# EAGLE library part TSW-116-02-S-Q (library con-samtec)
THROUGH-HOLE .025" SQ POST HEADER Source: Samtec TSW.pdf
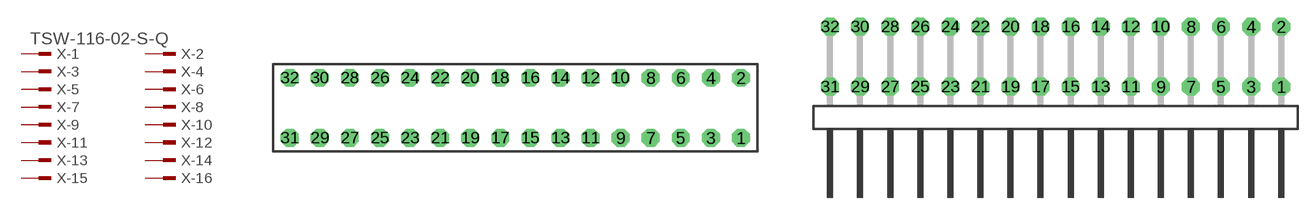
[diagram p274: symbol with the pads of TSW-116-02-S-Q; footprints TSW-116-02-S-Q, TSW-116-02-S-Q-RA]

Designator prefix X; gates -1=MPINV -2=MPIN -3=MPIN -4=MPIN -5=MPIN -6=MPIN -7=MPIN -8=MPIN -9=MPIN -10=MPIN -11=MPIN -12=MPIN -13=MPIN -14=MPIN -15=MPIN -16=MPIN -17=MPIN -18=MPIN -19=MPIN -20=MPIN -21=MPIN -22=MPIN -23=MPIN -24=MPIN -25=MPIN -26=MPIN -27=MPIN -28=MPIN -29=MPIN -30=MPIN -31=MPIN -32=MPIN

## TSW-116-02-S-Q (OC_FARNELL: unknown; OC_NEWARK: unknown)  [TSW-116-02-S-Q]
1  -1:1  pas
2  -2:1  pas
3  -3:1  pas
4  -4:1  pas
5  -5:1  pas
6  -6:1  pas
7  -7:1  pas
8  -8:1  pas
9  -9:1  pas
10  -10:1  pas
11  -11:1  pas
12  -12:1  pas
13  -13:1  pas
14  -14:1  pas
15  -15:1  pas
16  -16:1  pas
17  -17:1  pas
18  -18:1  pas
19  -19:1  pas
20  -20:1  pas
21  -21:1  pas
22  -22:1  pas
23  -23:1  pas
24  -24:1  pas
25  -25:1  pas
26  -26:1  pas
27  -27:1  pas
28  -28:1  pas
29  -29:1  pas
30  -30:1  pas
31  -31:1  pas
32  -32:1  pas

## TSW-116-02-S-Q-RA (OC_FARNELL: unknown; OC_NEWARK: unknown)  [TSW-116-02-S-Q-RA]
Pads as for TSW-116-02-S-Q

## Footprint TSW-116-02-S-Q (pad centres in mm)
THROUGH-HOLE .025" SQ POST HEADER Source: Samtec TSW.pdf
drill 1 pad 1.5 octagon: 1 19.05,-2.54; 2 19.05,2.54; 3 16.51,-2.54; 4 16.51,2.54; 5 13.97,-2.54; 6 13.97,2.54; 7 11.43,-2.54; 8 11.43,2.54; 9 8.89,-2.54; 10 8.89,2.54; 11 6.35,-2.54; 12 6.35,2.54; 13 3.81,-2.54; 14 3.81,2.54; 15 1.27,-2.54; 16 1.27,2.54; 17 -1.27,-2.54; 18 -1.27,2.54; 19 -3.81,-2.54; 20 -3.81,2.54; 21 -6.35,-2.54; 22 -6.35,2.54; 23 -8.89,-2.54; 24 -8.89,2.54; 25 -11.43,-2.54; 26 -11.43,2.54; 27 -13.97,-2.54; 28 -13.97,2.54; 29 -16.51,-2.54; 30 -16.51,2.54; 31 -19.05,-2.54; 32 -19.05,2.54

## Footprint TSW-116-02-S-Q-RA (pad centres in mm)
THROUGH-HOLE .025" SQ POST HEADER Source: Samtec TSW.pdf
drill 1 pad 1.5 octagon: 1 19.05,1.524; 2 19.05,6.604; 3 16.51,1.524; 4 16.51,6.604; 5 13.97,1.524; 6 13.97,6.604; 7 11.43,1.524; 8 11.43,6.604; 9 8.89,1.524; 10 8.89,6.604; 11 6.35,1.524; 12 6.35,6.604; 13 3.81,1.524; 14 3.81,6.604; 15 1.27,1.524; 16 1.27,6.604; 17 -1.27,1.524; 18 -1.27,6.604; 19 -3.81,1.524; 20 -3.81,6.604; 21 -6.35,1.524; 22 -6.35,6.604; 23 -8.89,1.524; 24 -8.89,6.604; 25 -11.43,1.524; 26 -11.43,6.604; 27 -13.97,1.524; 28 -13.97,6.604; 29 -16.51,1.524; 30 -16.51,6.604; 31 -19.05,1.524; 32 -19.05,6.604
